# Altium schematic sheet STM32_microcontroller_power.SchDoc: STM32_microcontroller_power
size A4; Date: Not used; ApprovedBy: Not used; CheckedBy: Not used; Author: Not used; CompanyName: STMicroelectronics; DrawnBy: Not used; Engineer: Not used; Organization: Not used; Address1: Not used; Address2: Not used; Address3: Not used; Address4: Not used; DocumentNumber: 4; Revision: Not used; SheetNumber: 4; SheetTotal: 8
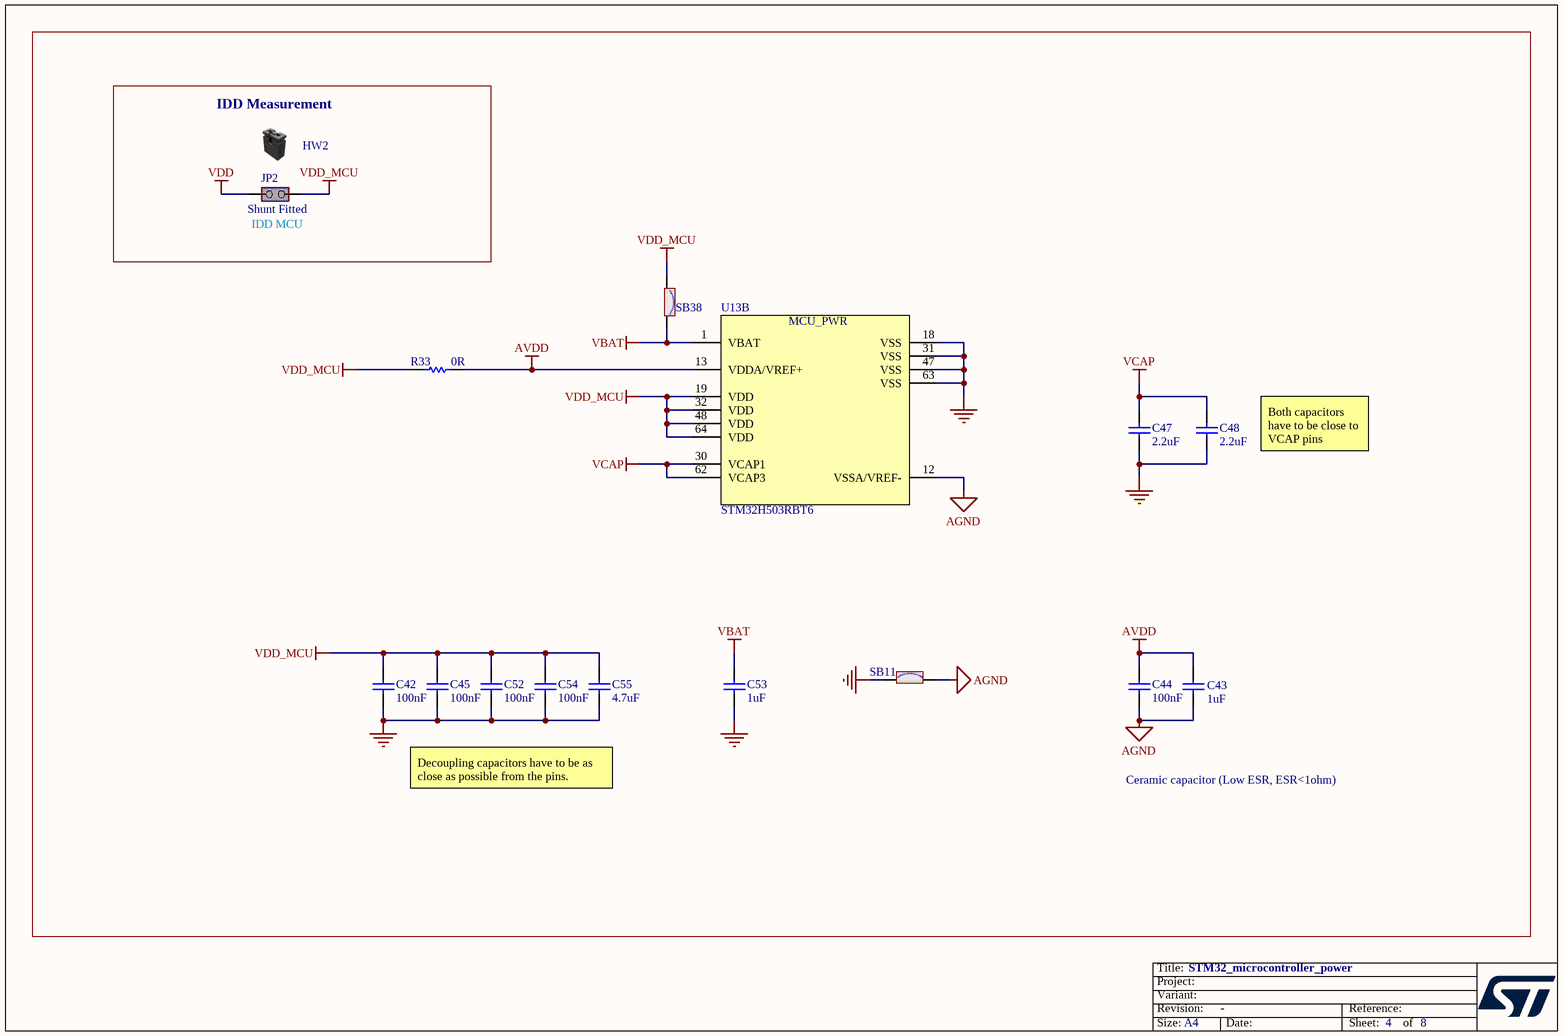
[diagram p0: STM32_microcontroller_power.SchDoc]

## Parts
C42  value 100nF  [C0402]  (hidden comment: Capacitor)
C43  value 1uF  [C0603]
C44  value 100nF  [C0402]  (hidden comment: Capacitor)
C45  value 100nF  [C0402]  (hidden comment: Capacitor)
C47  value 2.2uF  [C0603]  (hidden comment: Capacitor)
C48  value 2.2uF  [C0603]  (hidden comment: Capacitor)
C52  value 100nF  [C0402]  (hidden comment: Capacitor)
C53  value 1uF  [C0603]
C54  value 100nF  [C0402]  (hidden comment: Capacitor)
C55  value 4.7uF  [C0603]
HW2  (no value)  (mechanical)
JP2  Shunt Fitted  [CON_SAMTEC_TSW-102-07-G-S]
R33  value 0R  [R0603]  (hidden comment: Resistor)
SB11  (no value)  [SOLDER-BRIDGE_R0603-0R]
SB38  (no value)  [SOLDER-BRIDGE_R0603-0R]
U13  value STM32H503RBT6  [ICC_LQFP64_10X10_P050_SOCKET_YAMAICHI_IC149-064-069-B5_NM]  (hidden comment: STM32H503RBH6)  (part B of 2)

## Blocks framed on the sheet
IDD Measurement: HW2 JP2

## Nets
AGND: C43.1 C44.1 SB11.2 U13.12(VSSA/VREF-)
AVDD: C43.2 C44.2 R33.2 U13.13(VDDA/VREF+)
GND: C42.1 C45.1 C47.1 C48.1 C52.1 C53.1 C54.1 C55.1 SB11.1 U13.18(VSS) U13.31(VSS) U13.47(VSS) U13.63(VSS)
VBAT: C53.2 SB38.2 U13.1(VBAT)
VCAP: C47.2 C48.2 U13.30(VCAP1) U13.62(VCAP3)
VDD: JP2.1(COMMON)
VDD_MCU: C42.2 C45.2 C52.2 C54.2 C55.2 JP2.2(NO) R33.1 SB38.1 U13.19(VDD) U13.32(VDD) U13.48(VDD) U13.64(VDD)

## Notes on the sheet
- (near JP2) IDD MCU
- Both capacitors have to be close to VCAP pins
- Decoupling capacitors have to be as close as possible from the pins.
- Ceramic capacitor (Low ESR, ESR<1ohm)

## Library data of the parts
C42 C44 C45 C52 C54 = MCD-00006: Capacitor, MLCC, 100nF, 16V, X7R, +/-10%, 0402, T=0.5mm; Part_Preference: Recommended; Manufacturer: YAGEO; Manufacturer_Part_Number: CC0402KRX7R7BB104; Partial_Alternate_Internal_Part_Number: MCD-03299; Order_Code_RS: 9402047; Component_Country_Of_Origin: China; ShowFields: YES; ID: 2474
C43 C53 = MCD-00010: Capacitor, MLCC, 1uF, 16V, X5R, 10%, 0603, T=0,8mm; Manufacturer_Part_Number: CC0603KRX5R7BB105; Manufacturer: YAGEO; Provided_By: Subcon; Initial_Board_Reference: MB1274
C47 C48 = MCD-00012: Capacitor, MLCC, 2.2uF, 10V, X5R, +/- 10%, 0603, T=0,8mm; BMS_Part_Number: 9142010; Part_Preference: Recommended; Manufacturer: YAGEO; Manufacturer_Part_Number: CC0603KRX5R6BB225; Alternate_Manufacturer: KEMET; Alternate_Manufacturer_Part_Number: C0603C225K8PACTU
C55 = MCD-00009: Capacitor, MLCC, 4.7uF, 16V, X5R, 10%, 0603, T=0.8mm; Manufacturer_Part_Number: CC0603KRX5R7BB475; Manufacturer: YAGEO; Provided_By: subcon; Initial_Board_Reference: MB1274
HW2 = MCD-00043: SHUNT 2.54mm BLACK; Manufacturer_Part_Number: SNT-100-BK-G; Manufacturer: SAMTEC; Part_Type: Mechanical; Provided_By: Subcon; Initial_Board_Reference: MB1274
JP2 = MCD-00683: Header, 2x1, 2,54mm, VR, TH, Height 5.84mm/2.54mm - Shunt Fitted by default; Part_Type: Connector; Manufacturer_Part_Number: TSW-102-07-x-S; Manufacturer: SAMTEC; Provided_By: Subcon; Initial_Board_Reference: MB1331
R33 = MCD-00056: Resistor, 0R, 0603, +/-5%, 1/10W; Part_Preference: Recommended; Manufacturer: YAGEO; Manufacturer_Part_Number: RC0603JR-070RL
SB11 SB38 = MCD-00071: Solder Bridge ON; Part_Type: Mechanical; Manufacturer_Part_Number: RC0603JR-070RL; Manufacturer: YAGEO; Provided_By: SUBCO
U13 = MCD-02438: MCU, Arm Cortex-M33, 250MHz, 32-bit MCU, 128KB flash, 32KB SRAM; Part_Type: IC; Part_Preference: Recommended; Manufacturer: STMICROELECTRONICS; ShowFields: YES; ID: 4544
